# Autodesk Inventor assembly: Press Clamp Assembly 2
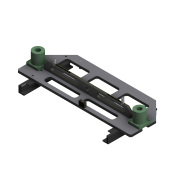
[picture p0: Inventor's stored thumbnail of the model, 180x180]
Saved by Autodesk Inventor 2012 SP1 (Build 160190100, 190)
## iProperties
Shininess: 0.0
Created: 2000-06
Part Number: Press Clamp Assembly 2
Document SubType Name: Assembly
Designer: Ron
Density: 2.3006381189633704
Volumn: 2438.720532206844
Area: 5070.810441262498
PropertySet Name: Model Information
Control State: 0
Master: False
Checked Out: False
Author: Ron
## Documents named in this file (13)
- D:\AOTC\Autodesk Inventor 2012 Essential for New Users\Autodesk Inventor 2012 Essentials - Project Files\Learning\Workspace\Sub-Assemblies\Press Clamp Assembly 2.iam
- D:\AOTC\Autodesk Inventor 2012 Essential for New Users\Autodesk Inventor 2012 Essentials - Project Files\Learning\Workspace\Parts\stiffener.ipt
- D:\AOTC\Autodesk Inventor 2012 Essential for New Users\Autodesk Inventor 2012 Essentials - Project Files\Learning\Workspace\Parts\bearing plate.ipt
- D:\AOTC\Autodesk Inventor 2012 Essential for New Users\Autodesk Inventor 2012 Essentials - Project Files\Learning\Workspace\Parts\TLM-815.ipt
- D:\AOTC\Autodesk Inventor 2012 Essential for New Users\Autodesk Inventor 2012 Essentials - Project Files\Learning\Workspace\Libraries\Content Center Files\en-US\0BE8FA95-308B-623F-04D4-EFB47B630795.ipt
- D:\AOTC\Autodesk Inventor 2012 Essential for New Users\Autodesk Inventor 2012 Essentials - Project Files\Learning\Workspace\Parts\vac-plate guide_RH.ipt
- D:\AOTC\Autodesk Inventor 2012 Essential for New Users\Autodesk Inventor 2012 Essentials - Project Files\Learning\Workspace\Parts\vac-plate guide.ipt
- D:\AOTC\Autodesk Inventor 2012 Essential for New Users\Autodesk Inventor 2012 Essentials - Project Files\Learning\Workspace\Libraries\Content Center Files\en-US\9ECBB5A1-AADB-6BAA-27F0-96D7996E1213.ipt
- D:\AOTC\Autodesk Inventor 2012 Essential for New Users\Autodesk Inventor 2012 Essentials - Project Files\Learning\Workspace\Parts\LE-067E-11.ipt
- D:\AOTC\Autodesk Inventor 2012 Essential for New Users\Autodesk Inventor 2012 Essentials - Project Files\Learning\Workspace\Libraries\Content Center Files\en-US\7CF39339-F6F1-C638-B5DF-5F301C69E554.ipt
- D:\AOTC\Autodesk Inventor 2012 Essential for New Users\Autodesk Inventor 2012 Essentials - Project Files\Learning\Workspace\Parts\press latch block.ipt
- D:\AOTC\Autodesk Inventor 2012 Essential for New Users\Autodesk Inventor 2012 Essentials - Project Files\Learning\Workspace\Sub-Assemblies\detent-01.iam
- C:\Documents and Settings\All Users\Autodesk Learning\Inventor 11\Introduction to 3D Design\Components\detent.iam
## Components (19 placed, 12 different names)
1. bearing plate:1 — Mate:19, Flush:5, Mate:20, Insert:33, Insert:34, Mate:24, Mate:25, Angle:3, Mate:26, Mate:29, Angle:4, Insert:38, Insert:39, Insert:40, Insert:41, Mate:30, Mate:35, Flush:12, Flush:13, Mate:42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
2. TLM-815:1 — Mate:19, Flush:5, Mate:20
3. TLM-8125a:1 — Mate:42, Angle:6, Mate:43
4. stiffener:1 — Mate:35, Flush:12, Flush:13, Mate:37, Mate:38, Mate:34, Insert:43
5. vac-plate guide.ipt:2 — Mate:26, Mate:29, Angle:4, Flush:9, Mate:41
6. Pin - Unhardened Ground Dowel - 1/2 x 1 1/2:1 — Insert:33
7. Pin - Unhardened Ground Dowel - 1/2 x 1 1/2:2 — Insert:34
8. Pin - Unhardened Ground Dowel - 1/4 x 3/4:1 — Insert:41
9. Pin - Unhardened Ground Dowel - 1/4 x 3/4:2 — Insert:40
10. Pin - Unhardened Ground Dowel - 1/4 x 3/4:3 — Insert:39
11. Pin - Unhardened Ground Dowel - 1/4 x 3/4:4 — Insert:38
12. Pin - Hardened Ground Production Dowel - 1/8 x 3/4:2 — Mate:32, Flush:11, Mate:34
13. Pin - Hardened Ground Production Dowel - 1/8 x 3/4:1 — Mate:33, Flush:11, Insert:43
14. LE-067E-11:2 — Mate:32, Mate:37
15. LE-067E-11:1 — Mate:33, Mate:38
16. press latch block:1 — Mate:24, Mate:25, Angle:3
17. vac-plate guide_RH:1 — Flush:9, Flush:10, Mate:30, Mate:39, Mate:40, Angle:5
18. detent-01:1 [sub-assembly] — Mate:39, Mate:40, Angle:5, Flush:17, Flush:18
19. detent-01:2 [sub-assembly] — Mate:41, Flush:17, Flush:18
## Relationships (37: Mate 18, Flush 8, Insert 7, Angle 4)
- Mate:19: bearing plate:1 ↔ TLM-815:1
- Flush:5: bearing plate:1 ↔ TLM-815:1
- Mate:20: bearing plate:1 ↔ TLM-815:1
- Insert:33: bearing plate:1 ↔ Pin - Unhardened Ground Dowel - 1/2 x 1 1/2:1
- Insert:34: bearing plate:1 ↔ Pin - Unhardened Ground Dowel - 1/2 x 1 1/2:2
- Mate:24: bearing plate:1 ↔ press latch block:1
- Mate:25: bearing plate:1 ↔ press latch block:1
- Angle:3: bearing plate:1 ↔ press latch block:1
- Mate:26: bearing plate:1 ↔ vac-plate guide.ipt:2
- Mate:29: bearing plate:1 ↔ vac-plate guide.ipt:2
- Angle:4: bearing plate:1 ↔ vac-plate guide.ipt:2
- Insert:38: bearing plate:1 ↔ Pin - Unhardened Ground Dowel - 1/4 x 3/4:4
- Insert:39: bearing plate:1 ↔ Pin - Unhardened Ground Dowel - 1/4 x 3/4:3
- Insert:40: bearing plate:1 ↔ Pin - Unhardened Ground Dowel - 1/4 x 3/4:2
- Insert:41: bearing plate:1 ↔ Pin - Unhardened Ground Dowel - 1/4 x 3/4:1
- Flush:9: vac-plate guide.ipt:2 ↔ vac-plate guide_RH:1
- Flush:10: vac-plate guide_RH:1
- Mate:30: bearing plate:1 ↔ vac-plate guide_RH:1
- Mate:32: Pin - Hardened Ground Production Dowel - 1/8 x 3/4:2 ↔ LE-067E-11:2
- Mate:33: Pin - Hardened Ground Production Dowel - 1/8 x 3/4:1 ↔ LE-067E-11:1
- Flush:11: Pin - Hardened Ground Production Dowel - 1/8 x 3/4:2 ↔ Pin - Hardened Ground Production Dowel - 1/8 x 3/4:1
- Mate:35: bearing plate:1 ↔ stiffener:1
- Flush:12: bearing plate:1 ↔ stiffener:1
- Flush:13: bearing plate:1 ↔ stiffener:1
- Mate:37: stiffener:1 ↔ LE-067E-11:2
- Mate:38: stiffener:1 ↔ LE-067E-11:1
- Mate:34: stiffener:1 ↔ Pin - Hardened Ground Production Dowel - 1/8 x 3/4:2
- Insert:43: stiffener:1 ↔ Pin - Hardened Ground Production Dowel - 1/8 x 3/4:1
- Mate:39: vac-plate guide_RH:1 ↔ detent-01:1
- Mate:40: vac-plate guide_RH:1 ↔ detent-01:1
- Angle:5: vac-plate guide_RH:1 ↔ detent-01:1
- Mate:41: vac-plate guide.ipt:2 ↔ detent-01:2
- Flush:17: detent-01:1 ↔ detent-01:2
- Flush:18: detent-01:1 ↔ detent-01:2
- Mate:42: bearing plate:1 ↔ TLM-8125a:1
- Angle:6: bearing plate:1 ↔ TLM-8125a:1
- Mate:43: bearing plate:1 ↔ TLM-8125a:1
